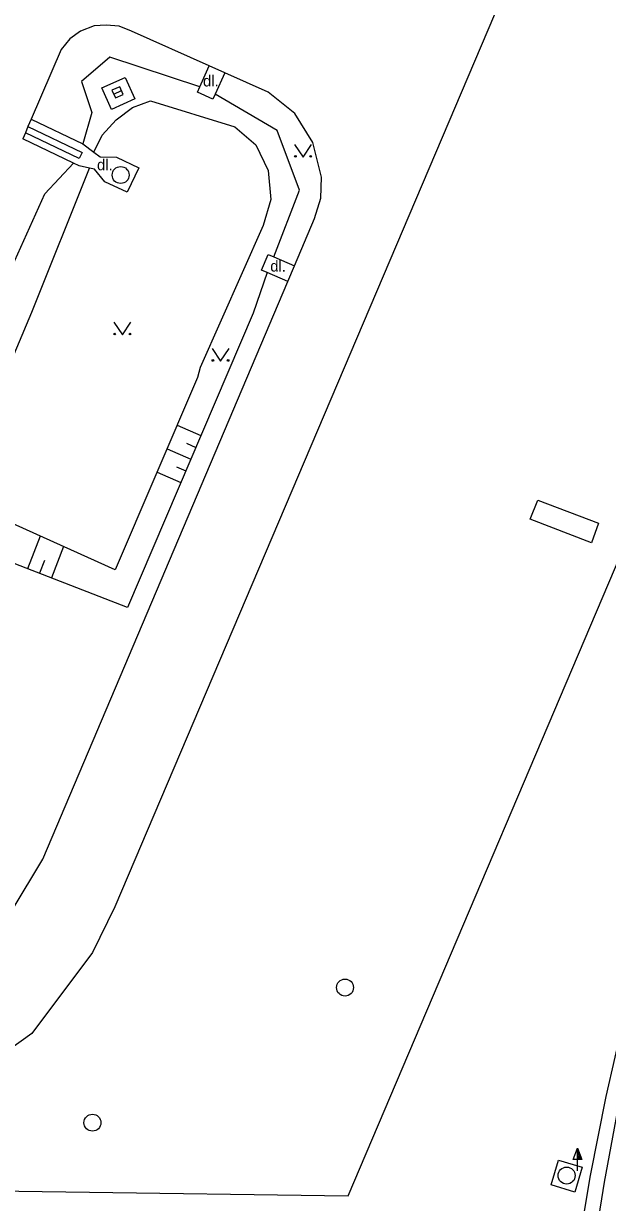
# Model space of a CAD drawing. Extents: x -596024 to -594475, y -1163820 to -1161957.
# Drawn here: x -594919.3 to -594884.9, y -1162691.2 to -1162621.8 of the extents above; entities that cross this region are included whole.
import ezdxf

# ---------------------------------------------------------------- set-up
doc = ezdxf.new("R2010")
doc.units = 0
for name, color, linetype in [('Level 10', 7, 'Continuous'), ('Level 11', 7, 'Continuous'), ('Level 14', 7, 'Continuous'), ('Level 15', 7, 'Continuous'), ('Level 25', 7, 'Continuous'), ('Level 27', 7, 'Continuous'), ('Level 36', 7, 'Continuous'), ('Level 40', 7, 'Continuous'), ('Level 7', 7, 'Continuous')]:
    doc.layers.add(name, color=color, linetype=linetype)

msp = doc.modelspace()

# ---------------------------------------------------------------- linework, layer by layer
at = {"layer": 'Level 10'}
for points in [[(-594846.75, -1162542.58), (-594847.02, -1162542.51), (-594848.96, -1162542.18), (-594851.99, -1162542.41), (-594854.86, -1162543.36), (-594857.46, -1162544.9), (-594859.6, -1162547.02), (-594861.11, -1162549.64), (-594913.9, -1162673.81), (-594915.2, -1162676.51), (-594918.78, -1162681.28), (-594923.61, -1162684.75), (-594929.28, -1162686.54), (-594935.26, -1162686.74), (-594950.08, -1162684.51), (-594952.91, -1162683.6), (-595041.5, -1162645.93), (-594955.82, -1162444.57), (-594948.99, -1162428.46), (-594885.06, -1162455.63)], [(-594908.33, -1162624.25), (-594912.91, -1162622.21), (-594913.63, -1162621.91), (-594914.4, -1162621.85), (-594915.11, -1162621.89), (-594915.92, -1162622.22), (-594916.54, -1162622.66), (-594917.06, -1162623.3), (-594918.82, -1162627.39)], [(-594907.42, -1162624.66), (-594908.33, -1162624.25)], [(-594903.31, -1162636.04), (-594902.13, -1162633.25), (-594901.76, -1162632.06), (-594901.72, -1162630.81), (-594902.23, -1162628.78), (-594903.3, -1162627.06), (-594904.87, -1162625.8), (-594907.42, -1162624.66)], [(-594919.01, -1162627.84), (-594919.16, -1162628.2)], [(-594918.82, -1162627.39), (-594919.01, -1162627.84)], [(-594919.16, -1162628.2), (-594919.31, -1162628.55)], [(-594903.7, -1162636.96), (-594903.31, -1162636.04)], [(-594938.43, -1162678.27), (-594932.46, -1162679.03), (-594928.71, -1162678.94), (-594924.63, -1162677.77), (-594922.09, -1162676.14), (-594919.94, -1162674.02), (-594918.14, -1162671.01), (-594903.7, -1162636.96)]]:
    msp.add_lwpolyline(points, dxfattribs=at)
at = {"layer": 'Level 11'}
for points in [[(-594908.89, -1162625.5), (-594908.33, -1162624.25)], [(-594914.65, -1162625.55), (-594913.28, -1162624.94), (-594912.71, -1162626.21), (-594914.08, -1162626.82), (-594914.65, -1162625.55)], [(-594907.42, -1162624.66), (-594907.99, -1162625.92)], [(-594907.99, -1162625.92), (-594908.12, -1162626.22), (-594909.03, -1162625.81), (-594908.89, -1162625.5)], [(-594900.15, -1162690.86), (-594881.96, -1162648.03), (-594872.93, -1162627.27)], [(-594919.01, -1162627.84), (-594915.82, -1162629.36), (-594915.99, -1162629.72), (-594919.16, -1162628.2)], [(-594918.82, -1162627.39), (-594915.78, -1162628.86)], [(-594916.32, -1162629.99), (-594919.31, -1162628.55)], [(-594915.78, -1162628.86), (-594915.13, -1162629.34)], [(-594915.13, -1162629.34), (-594914.75, -1162629.62), (-594913.8, -1162629.64), (-594912.48, -1162630.26), (-594913.16, -1162631.71), (-594914.48, -1162631.09), (-594915.09, -1162630.34), (-594915.39, -1162630.28)], [(-594915.39, -1162630.28), (-594916, -1162630.15), (-594916.32, -1162629.99)], [(-594904.93, -1162636.44), (-594905.25, -1162636.3), (-594904.86, -1162635.38), (-594904.54, -1162635.52)], [(-594904.54, -1162635.52), (-594903.31, -1162636.04)], [(-594903.7, -1162636.96), (-594904.93, -1162636.44)], [(-594888.99, -1162649.85), (-594885.42, -1162651.21), (-594885.83, -1162652.37), (-594889.43, -1162650.98), (-594888.99, -1162649.85)], [(-594888.21, -1162690.21), (-594887.77, -1162688.75)], [(-594887.77, -1162688.75), (-594886.38, -1162689.17)], [(-594886.38, -1162689.17), (-594886.81, -1162690.63)], [(-594886.81, -1162690.63), (-594888.21, -1162690.21)]]:
    msp.add_lwpolyline(points, dxfattribs=at)
at = {"layer": 'Level 14'}
for points in [[(-594908.89, -1162625.5), (-594914.19, -1162623.74), (-594915.85, -1162625.17), (-594915.25, -1162627), (-594915.78, -1162628.86)], [(-594915.13, -1162629.34), (-594914.63, -1162628.35), (-594913.82, -1162627.43), (-594912.85, -1162626.72), (-594911.79, -1162626.32), (-594906.82, -1162627.85), (-594905.59, -1162628.91), (-594904.86, -1162630.43), (-594904.7, -1162632.14), (-594905.16, -1162633.66), (-594908.86, -1162642.04), (-594909.03, -1162642.63), (-594913.87, -1162653.96), (-594922.34, -1162650.15), (-594922.59, -1162647.79), (-594918.78, -1162638.78), (-594915.39, -1162630.28)], [(-594904.54, -1162635.52), (-594903.01, -1162631.58), (-594904.34, -1162628.07), (-594907.99, -1162625.92)], [(-594904.93, -1162636.44), (-594905.74, -1162638.84), (-594913.15, -1162656.17), (-594924.13, -1162651.91), (-594925.99, -1162650.33), (-594925.46, -1162648.31), (-594921.74, -1162640.05), (-594918.01, -1162631.79), (-594916.32, -1162629.99)], [(-594883.93, -1162680.37), (-594884.99, -1162685)], [(-594884.99, -1162685), (-594885.9, -1162689.66)], [(-594884.19, -1162685.28), (-594885.08, -1162690.05)], [(-594885.9, -1162689.66), (-594886.37, -1162692.47)], [(-594885.08, -1162690.05), (-594885.49, -1162692.62)]]:
    msp.add_lwpolyline(points, dxfattribs=at)
at = {"layer": 'Level 15'}
for points in [[(-594910.23, -1162645.44), (-594908.82, -1162646.05)], [(-594909.68, -1162646.5), (-594909.12, -1162646.74)], [(-594910.82, -1162646.82), (-594909.41, -1162647.43)], [(-594910.27, -1162647.88), (-594909.71, -1162648.12)], [(-594911.41, -1162648.2), (-594910, -1162648.81)], [(-594918.29, -1162651.97), (-594919.03, -1162653.89)], [(-594916.92, -1162652.59), (-594917.63, -1162654.43)], [(-594918.04, -1162653.41), (-594918.33, -1162654.16)]]:
    msp.add_lwpolyline(points, dxfattribs=at)
at = {"layer": 'Level 25'}
for p, q in [((-594886.902, -1162688.718), (-594886.65, -1162688.044)), ((-594886.65, -1162688.718), (-594886.902, -1162688.718)), ((-594886.65, -1162689.37), (-594886.65, -1162688.72))]:
    msp.add_line(p, q, dxfattribs=at)
for points in [[(-594886.4, -1162688.72), (-594886.65, -1162688.72), (-594886.65, -1162688.044), (-594886.65, -1162688.044)], [(-594886.457, -1162688.68), (-594886.61, -1162688.68), (-594886.61, -1162688.267)], [(-594886.515, -1162688.64), (-594886.57, -1162688.64), (-594886.57, -1162688.491)]]:
    msp.add_lwpolyline(points, close=True, dxfattribs=at)
at = {"layer": 'Level 27'}
msp.add_line((-594913.958, -1162625.922), (-594913.502, -1162625.718), dxfattribs=at)
msp.add_lwpolyline([(-594913.856, -1162626.15), (-594913.4, -1162625.946), (-594913.604, -1162625.49), (-594914.06, -1162625.694)], close=True, dxfattribs=at)
for centre in [(-594913.55, -1162630.69), (-594900.34, -1162678.58), (-594915.21, -1162686.54), (-594887.29, -1162689.66)]:
    msp.add_circle(centre, 0.5, dxfattribs=at)
at = {"layer": 'Level 36'}
for points in [[(-594903.31, -1162628.89), (-594902.81, -1162629.64), (-594902.31, -1162628.89)], [(-594913.95, -1162639.36), (-594913.45, -1162640.11), (-594912.95, -1162639.36)], [(-594908.17, -1162640.92), (-594907.67, -1162641.67), (-594907.17, -1162640.92)]]:
    msp.add_lwpolyline(points, dxfattribs=at)
for centre in [(-594903.26, -1162629.59), (-594902.361, -1162629.59), (-594913.9, -1162640.06), (-594913.001, -1162640.06), (-594908.12, -1162641.62), (-594907.221, -1162641.62)]:
    msp.add_circle(centre, 0.05, dxfattribs=at)
at = {"layer": 'Level 7'}
msp.add_lwpolyline([(-595044.95, -1162641.91), (-595047.84, -1162648.63), (-594950.04, -1162690.15), (-594900.15, -1162690.86)], dxfattribs=at)

# ---------------------------------------------------------------- texts
at = {"layer": 'Level 40'}
for p in [(-594908.7, -1162625.47), (-594914.94, -1162630.41), (-594904.74, -1162636.38)]:
    msp.add_text('dl.', height=0.65, dxfattribs=at).set_placement(p)

doc.saveas('drawing.dxf')
